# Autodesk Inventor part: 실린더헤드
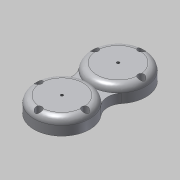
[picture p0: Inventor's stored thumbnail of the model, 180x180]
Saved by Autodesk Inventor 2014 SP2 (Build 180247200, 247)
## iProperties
Created: 2016-11
Part Number: 실린더헤드
Material: 알루미늄 6061
Document SubType Name: Modeling
Designer: mduedu
Density: 2.71 g/cm^3
Mass: 538.465 g
Surface Area: 423.673 cm^2
Volume: 198.695 cm^3
Appearance: 알루미늄 - 평지
Author: mduedu
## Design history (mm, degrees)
sketch "스케치1"
  geometry: C1 r 42 at (0, 0); 1 further point
  constraints: 1 centre point, 1 coincident
  dimensions: "d0" = 84 diameter of C1
extrude "돌출1" new body sketch "스케치1" distance "d1" = 24; taper "d2" = 0 deg
fillet "모깎기1" dims "d3" = 10
sketch "스케치2"
  geometry: C1 r 30 at (0, 0); 1 further point
  constraints: 1 centre point, 1 coincident
  dimensions: "d4" = 60 diameter of C1
extrude "돌출2" join sketch "스케치2" distance "d5" = 5; taper "d6" = 0 deg
sketch "스케치3"
  geometry: C1 r 25 at (0, 0); 1 further point
  constraints: 1 centre point, 1 coincident
  dimensions: "d7" = 50 diameter of C1
extrude "돌출3" cut sketch "스케치3" distance "d8" = 20; taper "d9" = 0 deg
hole "구멍1" diameter "d12" = 4.134; stored, may be unused: countersink angle "d16" = 90 deg, drill point angle "d18" = 118 deg; dims "d10" = 10, "d11" = 10, "d13" = 6, "d14" = 4, "d15" = 2, "d17" = 8
chamfer "모따기1" distance "d19" = 1; stored, may be unused: second distance "d20" = 2, angle "d21" = 45 deg
fillet "모깎기2" dims "d22" = 3
sketch "스케치4"
  geometry: C1 r 17.5 at (0, 0); 1 further point
  constraints: 1 centre point, 1 coincident
  dimensions: "d23" = 35 diameter of C1
extrude "돌출4" cut sketch "스케치4" distance "d24" = 2; taper "d25" = 0 deg
fillet "모깎기3" dims "d26" = 0.5
sketch "스케치5" dims "d32" = 70
  geometry: C1 r 5 at (0, 35); 3 further points
  constraints: 2 coincident, 2 vertical alignment, 1 centre point, 2 other
  dimensions: "d33" = 10 diameter of C1
extrude "돌출5" cut sketch "스케치5" distance "d34" = 10; taper "d35" = 0 deg
sketch "스케치6"
  geometry: A1 r 35 centre (0, -35) between (0, 0) and (-35, -35); 2 further points
  constraints: 3 point on circle, 2 horizontal alignment, 1 centre point, 1 coincident, 1 vertical alignment
  dimensions: "d39" = 70 diameter of A1
hole "구멍3" sketch "스케치6" at (0, 0), (-35, -35), (35, -35) diameter "d57" = 5.5; stored, may be unused: countersink angle "d61" = 90 deg, drill point angle "d63" = 118 deg; dims "d58" = 6, "d59" = 4, "d60" = 2, "d62" = 8
chamfer "모따기2" distance "d54" = 5; stored, may be unused: second distance "d55" = 2, angle "d56" = 30 deg
node "작업 평면1"
sketch "스케치8"
  geometry: L1 (0, 85)-(0, 0); A1 r 42 centre (0, 85) between (-32.469, 58.358) and (32.469, 58.358) reference; A2 r 42 centre (0, 0) between (-32.469, 26.642) and (32.469, 26.642) reference; A3 r 25 centre (51.795, 42.5) between (32.469, 26.642) and (32.469, 58.358); A4 r 25 centre (-51.795, 42.5) between (-32.469, 58.358) and (-32.469, 26.642); A5 r 25 centre (-51.795, 42.5) between (-32.469, 26.642) and (-32.469, 58.358); A6 r 25 centre (51.795, 42.5) between (32.469, 58.358) and (32.469, 26.642); A7 r 42 centre (0, 85) between (-32.469, 58.358) and (32.469, 58.358); A8 r 42 centre (0, 0) between (32.469, 26.642) and (-32.469, 26.642); 1 further point
  constraints: 16 point on circle, 6 centre point, 2 coincident, 2 end point, 2 tangent, 1 symmetric about line, 1 vertical, 1 other
  dimensions: "d65" = 50 diameter of A3
extrude "돌출6" join sketch "스케치8" distance "d67" = 14; taper "d68" = 0 deg
node "솔리드1"
pattern_circular "원형 패턴1" dims angle "d37" = 360 deg
mirror "대칭1"
other parameters: "d64" = 42.5
